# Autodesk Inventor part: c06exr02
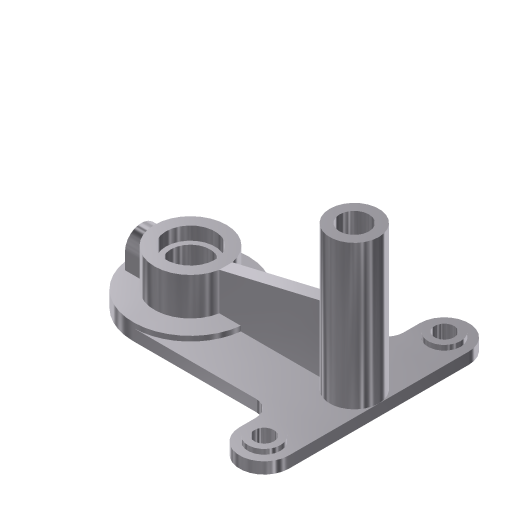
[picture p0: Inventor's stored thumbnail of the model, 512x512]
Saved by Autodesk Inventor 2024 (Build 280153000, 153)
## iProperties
Shininess: 77.0
Length Units: 11269
Angle Units: 11279
Time Units: 11290
Mass Units: 11283
Length Display Precision: 3
Angle Display Precision: 2
Created: 2001-12
Part Number: c06exr02
Document SubType Name: Modeling
Material: Generic
Density: 1 g/cm^3
Appearance: Metal-AL-6061 (Polished)
Density: 0.0
Volumn: 0.0
Area: 0.0
PropertySet Name: Model Information
Control State: 0
Master: False
Checked Out: False
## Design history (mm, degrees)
sketch "Sketch1"
  geometry: L1 (46.121, -53.4)-(46.121, 56.6); L2 (16.121, 56.6)-(16.121, 36.6); L3 (16.121, 36.6)-(-68.879, 36.6); L4 (-68.879, -33.4)-(16.121, -33.4); L5 (16.121, -33.4)-(16.121, -53.4); A1 r 15 centre (31.121, 56.6) between (46.121, 56.6) and (16.121, 56.6); A2 r 35 centre (-68.879, 1.6) between (-68.879, 36.6) and (-68.879, -33.4); A3 r 15 centre (31.121, -53.4) between (16.121, -53.4) and (46.121, -53.4)
  constraints: 10 end point, 6 point on circle, 5 tangent, 3 centre point, 3 parallel, 2 equal length, 1 equal radius, 1 perpendicular, 1 vertical
  dimensions: "d0" = 15 radius of A1; "d1" = 110 distance of L1.start L1.end; "d2" = 100 horizontal distance of A3.centre A2.centre; "d3" = 35 radius of A2
extrude "Extrusion1" new body sketch "Sketch1" distance "d4" = 7; taper "d5" = 0 deg
sketch "Sketch2"
  geometry: C1 r 10 at (31.121, 56.6); C2 r 10 at (31.121, -53.4); C3 r 35 at (-68.879, 1.6); A1 r 35 centre (-68.879, 1.6) between (-68.879, 36.6) and (-68.879, -33.4) reference; A2 r 15 centre (31.121, 56.6) between (46.121, 56.6) and (16.121, 56.6) reference; A3 r 15 centre (31.121, -53.4) between (16.121, -53.4) and (46.121, -53.4) reference
  constraints: 3 centre point, 3 concentric, 2 equal radius
  dimensions: "d45" = 20 diameter of C1
extrude "Extrusion2" join sketch "Sketch2" distance "d6" = 3; taper "d7" = 0 deg
sketch "Sketch3"
  geometry: C1 r 22 at (0, 0); 1 further point
  constraints: 1 centre point, 1 coincident
  dimensions: "d8" = 44 diameter of C1
extrude "Extrusion3" join sketch "Sketch3" distance "d9" = 23; taper "d10" = 0 deg
sketch "Sketch4"
  geometry: L1 (46.121, 56.6)-(46.121, -53.4) reference; L2 (-68.879, 36.6)-(16.121, 36.6) reference; C1 r 15 at (31.121, 1.6)
  constraints: 1 centre point
  dimensions: "d11" = 30 diameter of C1; "d12" = 15 distance from line of L1 C1.centre; "d13" = 35 distance from line of L2 C1.centre
extrude "Extrusion4" join sketch "Sketch4" distance "d14" = 88; taper "d15" = 0 deg
workplane "Work Plane1"
feature "Rib1" dims "d21" = 1, "d22" = 8
workplane "Work Plane2"
workplane "Work Plane3"
sketch "Sketch7"
  geometry: L1 (10, 0)-(10, 10); L2 (-10, 10)-(-10, 0); L3 (-10, 0)-(10, 0); L4 (55, -10)-(55, -3) reference; A1 r 10 centre (0, 10) between (10, 10) and (-10, 10); 2 further points
  constraints: 6 end point, 2 point on circle, 2 tangent, 1 centre point, 1 parallel, 1 perpendicular, 1 vertical
  dimensions: "d30" = 10 radius of A1; "d34" = 55 distance from line of L4 A1.centre; "d35" = 10 distance of L1.start L1.end
extrude "Extrusion6" join sketch "Sketch7" stored distance "d36" = 88; taper "d37" = 0 deg
sketch "Sketch8"
  geometry: C1 r 10 at (0, 0) reference
hole "Hole1" sketch "Sketch8" diameter "d38" = 12; stored, may be unused: countersink angle "d42" = 82 deg, drill point angle "d44" = 118 deg; dims "d39" = 6, "d40" = 4, "d41" = 2, "d43" = 8
mirror "Mirror1"
sketch "Sketch9"
  geometry: C1 r 10 at (0, 0)
  constraints: 1 centre point
hole "Hole2" sketch "Sketch9" diameter "d52" = 18; stored, may be unused: drill point angle "d47" = 118 deg, countersink angle "d48" = 82 deg; dims "d46" = 6, "d49" = 2, "d50" = 4, "d51" = 8
sketch "Sketch10"
  geometry: C1 r 10 at (0, 0)
  constraints: 1 centre point
hole "Hole3" sketch "Sketch10" diameter "d59" = 24; stored, may be unused: drill point angle "d54" = 118 deg, countersink angle "d55" = 82 deg; dims "d53" = 6, "d56" = 8, "d57" = 30, "d58" = 8
sketch "Sketch11"
  geometry: C1 r 10 at (0, 0)
  constraints: 1 centre point
hole "Hole4" sketch "Sketch11" diameter "d66" = 10; stored, may be unused: drill point angle "d61" = 0 deg, countersink angle "d62" = 82 deg; dims "d60" = 6, "d63" = 2, "d64" = 4, "d65" = 8
fillet "Fillet1" dims "d67" = 10
body "Solid1"
sketch "Sketch5"
  geometry: L1 (22, 33.1)-(85, 48); L2 (0, 7)-(35, 7) reference; L3 (85, 0)-(85, 7) reference; L4 (115, 0)-(115, 7) reference; L5 (115, 0)-(85, 0) reference
  constraints: 2 end point
  dimensions: "d17" = 26.1 distance from line of L2 L1.start; "d18" = 63 distance from line of L3 L1.start; "d19" = 30 distance from line of L4 L1.end; "d20" = 48 distance from line of L5 L1.end
other parameters: "d16" = -35, "d29" = -8
